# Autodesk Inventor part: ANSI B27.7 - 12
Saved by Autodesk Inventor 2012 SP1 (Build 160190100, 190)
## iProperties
Created: 2005-12
Part Number: ANSI B27.7 - 12
Material: Steel, Mild
Description: E-Ring External - Type-3CM
Vendor: Autodesk Inc.
Document SubType Name: Modeling
Standard: ANSI B27.7
Designer: t_munrn
Standards Organization: ANSI
Language: en-US
Size Designation: 12
Categories: <MemberInstance Version="R10.0.0"><Categories><Category DisplayName="Shaft Parts" InternalName="7f7aeb1f-a693-4053-b835-cee3144e0d98" Mnemonic="SHFT"><Category
Density: 1 g/cm^3
Author: t_munrn
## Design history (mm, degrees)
sketch "Sketch1"
  geometry: L1 (-1.03, 0.024)-(0, 0.024) reference; L2 (-13.02, 0)-(13.02, 0) reference; L3 (-4.72, -8.036)-(4.72, -8.036); L4 (0, 6.384)-(0, -15.036) reference; L5 (-6.18, -3.916)-(-5.171, -3.916); L6 (-1.03, 0.204)-(-1.03, 1.204); L7 (0, 3.324)-(2.53, 3.324); L8 (-4.72, -8.036)-(-5.532, -9.991); L9 (0, -0.826)-(-1.278, -0.826); L10 (4.72, -8.036)-(5.532, -9.991); L11 (6.18, -3.916)-(5.171, -3.916); L12 (1.03, 0.204)-(1.03, 1.204); C1 r 6 at (0, -5.976); A1 r 5.15 centre (0, -5.976) between (-4.878, -4.324) and (-4.72, -8.036); A2 r 1.03 centre (0, 0.204) between (-1.03, 0.204) and (1.03, 0.204); A3 r 9.3 centre (0, -5.976) between (8.346, -10.08) and (-8.346, -10.08); A4 r 8.24 centre (0, -5.976) between (-2.06, 2.002) and (-7.271, -2.099); A5 r 0.824 centre (-1.854, 1.204) between (-1.03, 1.204) and (-2.06, 2.002); A6 r 1.236 centre (-6.18, -2.68) between (-7.271, -2.099) and (-6.18, -3.916); A7 r 0.309 centre (-5.171, -4.225) between (-4.878, -4.324) and (-5.171, -3.916); A8 r 1.545 centre (-6.959, -9.399) between (-8.346, -10.08) and (-5.532, -9.991); A9 r 1.545 centre (6.959, -9.399) between (5.532, -9.991) and (8.346, -10.08); A10 r 5.15 centre (0, -5.976) between (4.72, -8.036) and (4.878, -4.324); A11 r 0.309 centre (5.171, -4.225) between (5.171, -3.916) and (4.878, -4.324); A12 r 1.236 centre (6.18, -2.68) between (6.18, -3.916) and (7.271, -2.099); A13 r 8.24 centre (0, -5.976) between (7.271, -2.099) and (2.06, 2.002); A14 r 0.824 centre (1.854, 1.204) between (2.06, 2.002) and (1.03, 1.204); 1 further point
  constraints: 30 point on circle, 20 end point, 15 centre point, 13 symmetric about line, 12 tangent, 8 point on line, 4 parallel, 2 coincident, 2 horizontal, 1 concentric, 1 perpendicular, 1 vertical alignment, 9 other
  dimensions: "d0" = 12 diameter of C1 (= WD); "d3" = 2.06 distance from line of A1.centre L3 (= 0.2 x ND); "d4" = 1.03 radius of A2 (= 0.1 x ND); "d5" = 18.6 diameter of A3 (= SD2); "d8" = 8.24 radius of A4 (= 0.8 x ND); "d9" = 2.06 distance from line of A1.centre L5 (= 0.2 x ND); "d10" = 0.824 radius of A5 (= 0.08 x ND); "d11" = 1.236 radius of A6 (= 0.12 x ND); "d12" = 0.309 radius of A7 (= 0.03 x ND); "d13" = 1.545 radius of A8 (= 0.15 x ND); "d14" = 5.15 distance from line of A1.centre L9 (= 0.5 x ND); "d15" = 5.15 radius of A1 (= 0.5 x ND)
extrude "Body" new body sketch "Sketch1" distance "d16" = 1.1 (= SD); taper "d17" = 0 deg
workaxis "Work Axis1"
workaxis "Work Axis2"
workplane "Work Plane1"
body "Solid1"
other parameters: "ND" = 10.3 [user parameter; used in 14 equation terms], "SD" = 1.1 [user parameter; used in 1 equation term], "WD" = 12 [user parameter; used in 1 equation term], "d1" = 16.48 (= 1.6 x ND), "d2" = 10.3 (= ND), "SD2" = 18.6 [user parameter; used in 1 equation term], "d6" = 10.3 (= ND), "d7" = 1.545 (= 0.15 x ND), "d18" = 0, "d19" = 0, "d27" = 0, "WDMIN" = 12 [user parameter], "WDMAX" = 13 [user parameter], "SNB" = 1.2 [user parameter], "BUBRMI" = 2.4 [user parameter]
